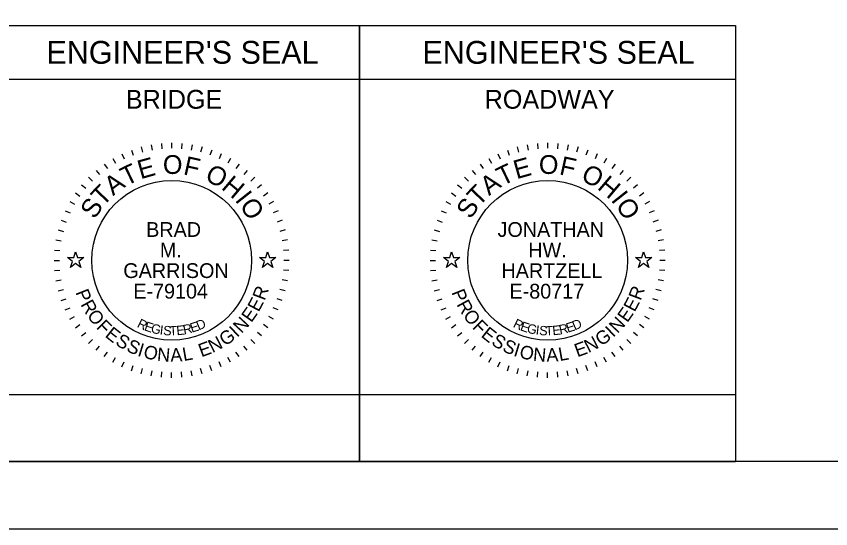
# Model space of a CAD drawing. Extents: x 0 to 45.9, y 0 to 22.
# Drawn here: x 23.84 to 29.91, y 0 to 3.82 of the extents above; entities that cross this region are included whole.
import ezdxf

# ---------------------------------------------------------------- set-up
doc = ezdxf.new("R2010")
doc.units = 0
for name, color, linetype in [('SH_Cut_Line', 7, 'Continuous'), ('SH_Data', 7, 'Continuous'), ('SH_Seal', 7, 'Continuous'), ('SH_Text', 7, 'Continuous')]:
    doc.layers.add(name, color=color, linetype=linetype)

msp = doc.modelspace()

# ---------------------------------------------------------------- linework, layer by layer
at = {"layer": 'SH_Cut_Line'}
for p, q in [((23.6, 3.75), (26.4, 3.75)), ((26.4, 3.75), (26.4, 0.5)), ((26.4, 0.5), (26.4, 3.75)), ((26.4, 3.75), (29.2, 3.75)), ((29.2, 3.75), (29.2, 0.5)), ((23.6, 3.35), (26.4, 3.35)), ((26.4, 3.35), (29.2, 3.35)), ((23.6, 0.5), (26.4, 0.5)), ((26.4, 0.5), (29.2, 0.5))]:
    msp.add_line(p, q, dxfattribs=at)
for points in [[(23.6, 0.5), (23.6, 1), (26.4, 1), (26.4, 0.5)], [(26.4, 0.5), (26.4, 1), (29.2, 1), (29.2, 0.5)]]:
    msp.add_lwpolyline(points, close=True, dxfattribs=at)
at = {"layer": 'SH_Data'}
msp.add_lwpolyline([(1.5, 21.5), (33.5, 21.5), (33.5, 0.5), (1.5, 0.5)], close=True, dxfattribs=at)
at = {"layer": 'SH_Seal'}
for p, q in [((24.8481, 2.8617), (24.855, 2.8223)), ((24.9237, 2.8717), (24.9272, 2.8318)), ((25, 2.875), (25, 2.835)), ((25.0763, 2.8717), (25.0728, 2.8318)), ((25.1519, 2.8617), (25.145, 2.8223)), ((27.6481, 2.8617), (27.655, 2.8223)), ((27.7237, 2.8717), (27.7272, 2.8318)), ((27.8, 2.875), (27.8, 2.835)), ((27.8763, 2.8717), (27.8728, 2.8318)), ((27.9519, 2.8617), (27.945, 2.8223)), ((24.6302, 2.793), (24.6471, 2.7568)), ((24.7007, 2.8222), (24.7144, 2.7846)), ((24.7735, 2.8452), (24.7839, 2.8065)), ((25.2265, 2.8452), (25.2161, 2.8065)), ((25.2993, 2.8222), (25.2856, 2.7846)), ((25.3698, 2.793), (25.3529, 2.7568)), ((27.4302, 2.793), (27.4471, 2.7568)), ((27.5007, 2.8222), (27.5144, 2.7846)), ((27.5735, 2.8452), (27.5839, 2.8065)), ((28.0265, 2.8452), (28.0161, 2.8065)), ((28.0993, 2.8222), (28.0856, 2.7846)), ((28.1698, 2.793), (28.1529, 2.7568)), ((24.5625, 2.7578), (24.5825, 2.7231)), ((25.4375, 2.7578), (25.4175, 2.7231)), ((27.3625, 2.7578), (27.3825, 2.7231)), ((28.2375, 2.7578), (28.2175, 2.7231)), ((24.4376, 2.6703), (24.4633, 2.6396)), ((24.4981, 2.7168), (24.5211, 2.684)), ((25.5019, 2.7168), (25.4789, 2.684)), ((25.5624, 2.6703), (25.5367, 2.6396)), ((27.2376, 2.6703), (27.2633, 2.6396)), ((27.2981, 2.7168), (27.3211, 2.684)), ((28.3019, 2.7168), (28.2789, 2.684)), ((28.3624, 2.6703), (28.3367, 2.6396)), ((24.3813, 2.6187), (24.4096, 2.5904)), ((25.6187, 2.6187), (25.5904, 2.5904)), ((27.1813, 2.6187), (27.2096, 2.5904)), ((28.4187, 2.6187), (28.3904, 2.5904)), ((24.3297, 2.5624), (24.3604, 2.5367)), ((25.6703, 2.5624), (25.6396, 2.5367)), ((27.1297, 2.5624), (27.1604, 2.5367)), ((28.4703, 2.5624), (28.4396, 2.5367)), ((24.2832, 2.5019), (24.316, 2.4789)), ((25.7168, 2.5019), (25.684, 2.4789)), ((27.0832, 2.5019), (27.116, 2.4789)), ((28.5168, 2.5019), (28.484, 2.4789)), ((24.2422, 2.4375), (24.2769, 2.4175)), ((25.7578, 2.4375), (25.7231, 2.4175)), ((27.0422, 2.4375), (27.0769, 2.4175)), ((28.5578, 2.4375), (28.5231, 2.4175)), ((24.207, 2.3698), (24.2432, 2.3529)), ((25.793, 2.3698), (25.7568, 2.3529)), ((27.007, 2.3698), (27.0432, 2.3529)), ((28.593, 2.3698), (28.5568, 2.3529)), ((24.1778, 2.2993), (24.2154, 2.2856)), ((25.8222, 2.2993), (25.7846, 2.2856)), ((26.9778, 2.2993), (27.0154, 2.2856)), ((28.6222, 2.2993), (28.5846, 2.2856)), ((24.1548, 2.2265), (24.1935, 2.2161)), ((25.8452, 2.2265), (25.8065, 2.2161)), ((26.9548, 2.2265), (26.9935, 2.2161)), ((28.6452, 2.2265), (28.6065, 2.2161)), ((24.1383, 2.1519), (24.1777, 2.145)), ((25.8617, 2.1519), (25.8223, 2.145)), ((26.9383, 2.1519), (26.9777, 2.145)), ((28.6617, 2.1519), (28.6223, 2.145)), ((24.1283, 2.0763), (24.1682, 2.0728)), ((25.8717, 2.0763), (25.8318, 2.0728)), ((26.9283, 2.0763), (26.9682, 2.0728)), ((28.6717, 2.0763), (28.6318, 2.0728)), ((24.125, 2), (24.165, 2)), ((25.875, 2), (25.835, 2)), ((26.925, 2), (26.965, 2)), ((28.675, 2), (28.635, 2)), ((24.1283, 1.9237), (24.1682, 1.9272)), ((25.8717, 1.9237), (25.8318, 1.9272)), ((26.9283, 1.9237), (26.9682, 1.9272)), ((28.6717, 1.9237), (28.6318, 1.9272)), ((24.1383, 1.8481), (24.1777, 1.855)), ((25.8617, 1.8481), (25.8223, 1.855)), ((26.9383, 1.8481), (26.9777, 1.855)), ((28.6617, 1.8481), (28.6223, 1.855)), ((24.1548, 1.7735), (24.1935, 1.7839)), ((25.8452, 1.7735), (25.8065, 1.7839)), ((26.9548, 1.7735), (26.9935, 1.7839)), ((28.6452, 1.7735), (28.6065, 1.7839)), ((24.1778, 1.7007), (24.2154, 1.7144)), ((25.8222, 1.7007), (25.7846, 1.7144)), ((26.9778, 1.7007), (27.0154, 1.7144)), ((28.6222, 1.7007), (28.5846, 1.7144)), ((24.207, 1.6302), (24.2432, 1.6471)), ((25.793, 1.6302), (25.7568, 1.6471)), ((27.007, 1.6302), (27.0432, 1.6471)), ((28.593, 1.6302), (28.5568, 1.6471)), ((24.2422, 1.5625), (24.2769, 1.5825)), ((25.7578, 1.5625), (25.7231, 1.5825)), ((27.0422, 1.5625), (27.0769, 1.5825)), ((28.5578, 1.5625), (28.5231, 1.5825)), ((24.2832, 1.4981), (24.316, 1.5211)), ((25.7168, 1.4981), (25.684, 1.5211)), ((27.0832, 1.4981), (27.116, 1.5211)), ((28.5168, 1.4981), (28.484, 1.5211)), ((24.3297, 1.4376), (24.3604, 1.4633)), ((25.6703, 1.4376), (25.6396, 1.4633)), ((27.1297, 1.4376), (27.1604, 1.4633)), ((28.4703, 1.4376), (28.4396, 1.4633)), ((24.3813, 1.3813), (24.4096, 1.4096)), ((25.6187, 1.3813), (25.5904, 1.4096)), ((27.1813, 1.3813), (27.2096, 1.4096)), ((28.4187, 1.3813), (28.3904, 1.4096)), ((24.4376, 1.3297), (24.4633, 1.3604)), ((25.5624, 1.3297), (25.5367, 1.3604)), ((27.2376, 1.3297), (27.2633, 1.3604)), ((28.3624, 1.3297), (28.3367, 1.3604)), ((24.4981, 1.2832), (24.5211, 1.316)), ((24.5625, 1.2422), (24.5825, 1.2769)), ((25.4375, 1.2422), (25.4175, 1.2769)), ((25.5019, 1.2832), (25.4789, 1.316)), ((27.2981, 1.2832), (27.3211, 1.316)), ((27.3625, 1.2422), (27.3825, 1.2769)), ((28.2375, 1.2422), (28.2175, 1.2769)), ((28.3019, 1.2832), (28.2789, 1.316)), ((24.6302, 1.207), (24.6471, 1.2432)), ((24.7007, 1.1778), (24.7144, 1.2154)), ((25.2993, 1.1778), (25.2856, 1.2154)), ((25.3698, 1.207), (25.3529, 1.2432)), ((27.4302, 1.207), (27.4471, 1.2432)), ((27.5007, 1.1778), (27.5144, 1.2154)), ((28.0993, 1.1778), (28.0856, 1.2154)), ((28.1698, 1.207), (28.1529, 1.2432)), ((24.7735, 1.1548), (24.7839, 1.1935)), ((24.8481, 1.1383), (24.855, 1.1777)), ((24.9237, 1.1283), (24.9272, 1.1682)), ((25, 1.125), (25, 1.165)), ((25.0763, 1.1283), (25.0728, 1.1682)), ((25.1519, 1.1383), (25.145, 1.1777)), ((25.2265, 1.1548), (25.2161, 1.1935)), ((27.5735, 1.1548), (27.5839, 1.1935)), ((27.6481, 1.1383), (27.655, 1.1777)), ((27.7237, 1.1283), (27.7272, 1.1682)), ((27.8, 1.125), (27.8, 1.165)), ((27.8763, 1.1283), (27.8728, 1.1682)), ((27.9519, 1.1383), (27.945, 1.1777)), ((28.0265, 1.1548), (28.0161, 1.1935))]:
    msp.add_line(p, q, dxfattribs=at)
for points in [[(24.2236, 2.02), (24.2705, 2.02), (24.285, 2.0645), (24.2995, 2.02), (24.3464, 2.02), (24.3085, 1.9924), (24.323, 1.9478), (24.285, 1.9754), (24.247, 1.9478), (24.2615, 1.9924)], [(25.6536, 2.02), (25.7005, 2.02), (25.715, 2.0645), (25.7295, 2.02), (25.7764, 2.02), (25.7385, 1.9924), (25.753, 1.9478), (25.715, 1.9754), (25.677, 1.9478), (25.6915, 1.9924)], [(27.0236, 2.02), (27.0705, 2.02), (27.085, 2.0645), (27.0995, 2.02), (27.1464, 2.02), (27.1085, 1.9924), (27.123, 1.9478), (27.085, 1.9754), (27.047, 1.9478), (27.0615, 1.9924)], [(28.4536, 2.02), (28.5005, 2.02), (28.515, 2.0645), (28.5295, 2.02), (28.5764, 2.02), (28.5385, 1.9924), (28.553, 1.9478), (28.515, 1.9754), (28.477, 1.9478), (28.4915, 1.9924)]]:
    msp.add_lwpolyline(points, close=True, dxfattribs=at)
for centre in [(25, 2), (27.8, 2)]:
    msp.add_circle(centre, 0.595, dxfattribs=at)
at = {"layer": 'SH_Text'}
msp.add_lwpolyline([(0, 0), (34, 0), (34, 22), (0, 22)], close=True, dxfattribs=at)

# ---------------------------------------------------------------- texts
at = {"layer": 'SH_Cut_Line'}
for s, height, p in [("ENGINEER'S SEAL", 0.17, (24.0676, 3.465)), ("ENGINEER'S SEAL", 0.17, (26.8676, 3.465)), ('BRIDGE', 0.14, (24.659, 3.13)), ('ROADWAY', 0.14, (27.3311, 3.13))]:
    msp.add_text(s, height=height, dxfattribs=at).set_placement(p)
at = {"layer": 'SH_Seal'}
for s, height, rotation, p in [('E', 0.14, 15.75706, (24.7684, 2.6038)), ('O', 0.14, 359.78119, (24.9347, 2.6443)), ('F', 0.14, 347.43619, (25.0811, 2.6417)), ('E', 0.14, 15.75706, (27.5684, 2.6038)), ('O', 0.14, 359.78119, (27.7347, 2.6443)), ('F', 0.14, 347.43619, (27.8811, 2.6417)), ('T', 0.14, 25.71674, (24.6616, 2.5518)), ('O', 0.14, 332.25863, (25.2398, 2.6015)), ('T', 0.14, 25.71674, (27.4616, 2.5518)), ('O', 0.14, 332.25863, (28.0398, 2.6015)), ('A', 0.14, 36.47472, (24.5634, 2.4781)), ('H', 0.14, 319.91363, (25.3632, 2.5361)), ('A', 0.14, 36.47472, (27.3634, 2.4781)), ('H', 0.14, 319.91363, (28.1632, 2.5361)), ('T', 0.14, 46.4344, (24.4883, 2.3964)), ('T', 0.14, 46.4344, (27.2883, 2.3964)), ('I', 0.14, 308.36695, (25.4665, 2.4483)), ('I', 0.14, 308.36695, (28.2665, 2.4483)), ('S', 0.14, 57.19238, (24.4281, 2.3014)), ('O', 0.14, 303.14906, (25.5021, 2.4089)), ('S', 0.14, 57.19238, (27.2281, 2.3014)), ('O', 0.14, 303.14906, (28.3021, 2.4089)), ('P', 0.1, 291.49398, (24.2823, 1.7621)), ('R', 0.1, 69.23216, (25.6919, 1.6954)), ('P', 0.1, 291.49398, (27.0823, 1.7621)), ('R', 0.1, 69.23216, (28.4919, 1.6954)), ('R', 0.1, 298.73106, (24.319, 1.6717)), ('E', 0.1, 61.99508, (25.6476, 1.6098)), ('R', 0.1, 298.73106, (27.119, 1.6717)), ('E', 0.1, 61.99508, (28.4476, 1.6098)), ('E', 0.1, 54.75801, (25.5933, 1.5314)), ('E', 0.1, 54.75801, (28.3933, 1.5314)), ('O', 0.1, 306.46664, (24.3655, 1.5883)), ('N', 0.1, 47.02243, (25.5202, 1.4508)), ('O', 0.1, 306.46664, (27.1655, 1.5883)), ('N', 0.1, 47.02243, (28.3202, 1.4508)), ('F', 0.1, 314.7068, (24.4343, 1.4983)), ('R', 0.07, 334.48695, (24.7375, 1.5051)), ('E', 0.07, 341.03996, (24.7906, 1.4801)), ('G', 0.07, 347.47515, (24.8414, 1.4618)), ('E', 0.07, 6.01169, (25.0389, 1.4412)), ('R', 0.07, 11.91844, (25.0925, 1.4474)), ('E', 0.07, 17.68363, (25.1498, 1.4602)), ('D', 0.07, 23.30524, (25.201, 1.477)), ('F', 0.1, 314.7068, (27.2343, 1.4983)), ('R', 0.07, 334.48695, (27.5375, 1.5051)), ('E', 0.07, 341.03996, (27.5906, 1.4801)), ('G', 0.07, 347.47515, (27.6414, 1.4618)), ('E', 0.07, 6.01169, (27.8389, 1.4412)), ('R', 0.07, 11.91844, (27.8925, 1.4474)), ('E', 0.07, 17.68363, (27.9498, 1.4602)), ('D', 0.07, 23.30524, (28.001, 1.477)), ('E', 0.1, 321.43929, (24.4978, 1.4348)), ('I', 0.07, 353.78581, (24.9091, 1.4468)), ('S', 0.07, 356.89262, (24.9358, 1.4429)), ('T', 0.07, 3.00609, (24.9857, 1.4387)), ('G', 0.1, 35.04687, (25.3981, 1.357)), ('I', 0.1, 43.28703, (25.4868, 1.4214)), ('E', 0.1, 321.43929, (27.2978, 1.4348)), ('I', 0.07, 353.78581, (27.7091, 1.4468)), ('S', 0.07, 356.89262, (27.7358, 1.4429)), ('T', 0.07, 3.00609, (27.7857, 1.4387)), ('G', 0.1, 35.04687, (28.1981, 1.357)), ('I', 0.1, 43.28703, (28.2868, 1.4214)), ('S', 0.1, 328.67637, (24.5743, 1.3752)), ('S', 0.1, 335.91345, (24.6564, 1.3266)), ('E', 0.1, 20.07421, (25.2212, 1.277)), ('N', 0.1, 27.31129, (25.3045, 1.3075)), ('S', 0.1, 328.67637, (27.3743, 1.3752)), ('S', 0.1, 335.91345, (27.4564, 1.3266)), ('E', 0.1, 20.07421, (28.0212, 1.277)), ('N', 0.1, 27.31129, (28.1045, 1.3075)), ('I', 0.1, 343.15053, (24.7406, 1.2897)), ('O', 0.1, 346.88592, (24.7839, 1.2751)), ('N', 0.1, 355.12608, (24.8888, 1.2517)), ('A', 0.1, 2.86166, (24.9923, 1.2437)), ('L', 0.1, 10.09874, (25.0894, 1.249)), ('I', 0.1, 343.15053, (27.5406, 1.2897)), ('O', 0.1, 346.88592, (27.5839, 1.2751)), ('N', 0.1, 355.12608, (27.6888, 1.2517)), ('A', 0.1, 2.86166, (27.7923, 1.2437)), ('L', 0.1, 10.09874, (27.8894, 1.249))]:
    msp.add_text(s, height=height, rotation=rotation, dxfattribs=at).set_placement(p)
for s, p in [('BRAD', (24.8104, 2.1749)), ('JONATHAN', (27.4271, 2.1749)), ('M.', (24.9126, 2.0216)), ('HW.', (27.6558, 2.0216)), ('GARRISON', (24.6401, 1.8684)), ('HARTZELL', (27.456, 1.8684)), ('E-79104', (24.7145, 1.7151)), ('E-80717', (27.5159, 1.7151))]:
    msp.add_text(s, height=0.11, dxfattribs=at).set_placement(p)

doc.saveas('drawing.dxf')
